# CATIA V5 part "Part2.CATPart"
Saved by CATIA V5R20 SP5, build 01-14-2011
Part number: Part2
Bounding box of the stored display mesh (mm): x -228.247 to 228.247, y -228.247 to 228.247, z -28.247 to 40.995
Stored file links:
  E:\180211216 李云飞\Part2.CATPart
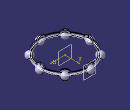
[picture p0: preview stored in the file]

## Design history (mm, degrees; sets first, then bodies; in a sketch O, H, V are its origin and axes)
Body1 (main body)
  Sketch1 on xy-plane, origin (0, 0, 0), H (1, 0, 0), V (0, 1, 0)
    circle A1 centre (0, 0) radius 200
  Pad1: profile Sketch1, direction (0, 0, 1), length 20
  Sketch2 on xy-plane, origin (0, 0, 0), H (1, 0, 0), V (0, 1, 0)
    circle A1 centre (0, 0) radius 193.1321
  Pocket1: profile Sketch2, direction (0, 0, 1), length 20
Body2
  Sketch3 on xy-plane, origin (0, 0, 0), H (1, 0, 0), V (0, 1, 0)
    arc A1 centre (200, 0) radius 36.0555 from (195, -35.7071) to (195, 35.7071) ccw
    point P1 (200, 0)
    axis line L1 (195, 110) -> (195, -110)
    point P4 (195, 35.7071)
    point P5 (195, -35.7071)
    distance L1 O = 195
    coincidence: P1 H, L1 P4, L1 P5
    vertical: L1 V
  Shaft1: profile Sketch3, axis Sketch3.L1, angle 360
  CircPattern1: of the body so far, instances 8, angular step 45, axis from end face of Pad1
  Sketch4 on xy-plane, origin (0, 0, 0), H (1, 0, 0), V (0, 1, 0)
    circle A1 centre (0, 0) radius 188.6796
  Sketch5 on xy-plane, origin (0, 0, 0), H (1, 0, 0), V (0, 1, 0)
    circle A1 centre (0, 0) radius 189.7367
  Pocket2: profile Sketch5, direction (0, 0, -1), length 60
  Sketch6 on xy-plane, origin (0, 0, 0), H (1, 0, 0), V (0, 1, 0)
    circle A1 centre (0, 0) radius 187.8829
  Pocket3: profile Sketch6, direction (0, 0, 1), length 60
  Sketch7 on xy-plane, origin (0, 0, 0), H (1, 0, 0), V (0, 1, 0)
    circle A1 centre (0, 0) radius 199.2486
  Sketch8 on xy-plane, origin (0, 0, 0), H (1, 0, 0), V (0, 1, 0)
    circle A1 centre (0, 0) radius 331.2099
  Pocket4: profile Sketch8, direction (0, 0, -1), length 60
  Sketch9 on xy-plane, origin (0, 0, 0), H (1, 0, 0), V (0, 1, 0)
    circle A1 centre (0, 0) radius 200
  Sketch10 on xy-plane, origin (0, 0, 0), H (1, 0, 0), V (0, 1, 0)
    circle A1 centre (0, 0) radius 197.2308
  Pocket5: profile Sketch10, direction (0, 0, 1), length 60, outer side
  Sketch11 on xy-plane, origin (0, 0, 0), H (1, 0, 0), V (0, 1, 0)
    circle A1 centre (0, 0) radius 193.1321
  Pocket6: profile Sketch11, direction (0, 0, -1), length 60
Body3
  Plane1: type Offset, RefPlane zx-plane, Offset 200
  Sketch12 on Plane1, origin (0, 200, 0), H (-1, 0, 0), V (0, 0, 1)
    arc A1 centre (0, 0) radius 28.2843 from (-28.2843, 0) to (28.2843, 0) ccw
    axis line L1 (120, 0) -> (-90, 0)
    point P1 (120, 0)
    point P3 (-28.2843, 0)
    point P4 (28.2843, 0)
    coincidence: P1 H, L1 P4, L1 P3
    horizontal: L1 H
  Shaft2: profile Sketch12, axis Sketch12.L1, angle 360
  CircPattern2: of Shaft2, instances 8, angular step 45, axis from face of Pad1 from Sketch1.A1
  Trim1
